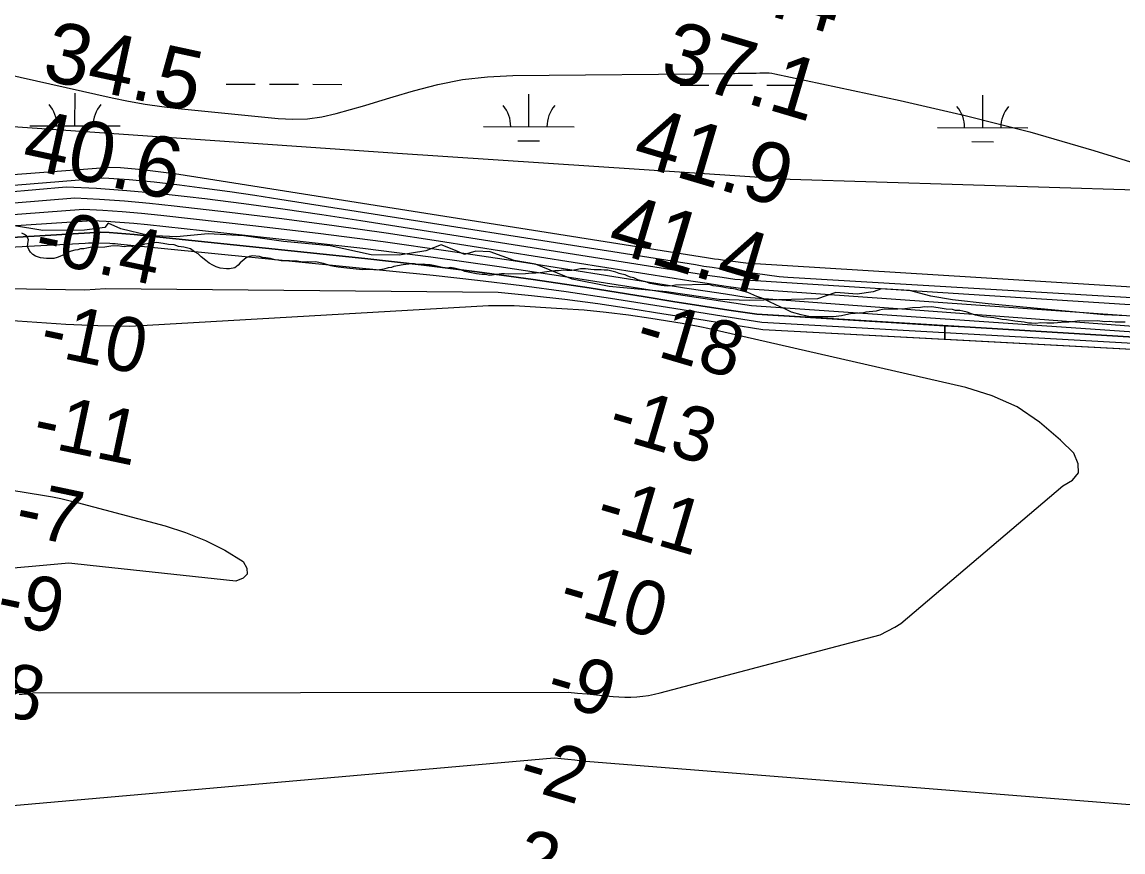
# Model space of a CAD drawing. Extents: x 3219052 to 3256913, y 800770 to 826146.
# Drawn here: x 3234446 to 3235663, y 812399 to 813316 of the extents above; entities that cross this region are included whole.
import ezdxf

# ---------------------------------------------------------------- set-up
doc = ezdxf.new("R2010")
doc.units = 0
for name, color, linetype in [('V-RIVR-EDGE', 7, 'Continuous'), ('V-RIVR-RANG', 7, 'Continuous'), ('V-SITE-VEGE', 7, 'Continuous'), ('V-TOPO-DPTH', 7, 'Continuous'), ('V-TOPO-MAJR', 7, 'Continuous'), ('V-TOPO-MINR', 7, 'Continuous'), ('V-TOPO-WATR', 7, 'Continuous'), ('V-WETL-SWMP', 7, 'Continuous')]:
    doc.layers.add(name, color=color, linetype=linetype)

msp = doc.modelspace()

# ---------------------------------------------------------------- linework, layer by layer
at = {"layer": 'V-RIVR-EDGE'}
for points in [[(3235514.1, 813004.7), (3235474.9, 813009.1), (3235450.8, 813013.5), (3235427.1, 813019.5), (3235396.3, 813021.6), (3235387.2, 813018), (3235369.4, 813015.7), (3235345.7, 813017.4), (3235325.5, 813010.3), (3235282.4, 813009.2), (3235250, 813008.5), (3235216.8, 813009.8), (3235158.7, 813018.2), (3235095.1, 813023.9), (3235054.4, 813032.3), (3235013.7, 813048.6), (3234990, 813052.6), (3234963.5, 813062.2), (3234947.7, 813063), (3234935, 813059.5), (3234925.2, 813063.9), (3234909.4, 813070.2), (3234892.3, 813063.5), (3234863.1, 813058.5), (3234831.8, 813058.9), (3234786.8, 813068.9), (3234735, 813073.8), (3234691.2, 813079.9), (3234651.6, 813082.3), (3234616.8, 813078.9), (3234585.6, 813080.5), (3234555.2, 813087.7), (3234541, 813094.1), (3234537.4, 813089.3), (3234514.9, 813086.2), (3234469, 813085.9), (3234435.4, 813091.6)], [(3237235.9, 812894.1), (3237149.3, 812895.9), (3236960.7, 812904.2), (3236846.1, 812912.4), (3236753.2, 812915.4), (3236688.4, 812916.8), (3236537.8, 812930.6), (3236373.4, 812945.2), (3236288.8, 812949.4), (3236142.9, 812959.6), (3235992.3, 812973.1), (3235916.8, 812980), (3235840.6, 812985.7), (3235793.5, 812987.8), (3235725.5, 812989.1), (3235642.5, 812992.5), (3235514.1, 813004.7)]]:
    msp.add_lwpolyline(points, dxfattribs=at)
at = {"layer": 'V-SITE-VEGE'}
for points in [[(3234570.5, 813067.3), (3234567.2, 813068.2), (3234562.9, 813068.6), (3234559.6, 813068), (3234556.3, 813068.4), (3234551.5, 813068.8), (3234543.9, 813068.7), (3234537.3, 813067.6), (3234521.2, 813067.3), (3234517.4, 813066.3), (3234514.1, 813065.7), (3234510.7, 813065.7), (3234507.4, 813064.7), (3234504.1, 813064.1), (3234500.3, 813063.1), (3234497, 813062.1), (3234491.4, 813058.6), (3234490.9, 813058.6), (3234487.6, 813057.2), (3234484.8, 813056.1), (3234481, 813055.1), (3234473, 813055), (3234466.3, 813055.8), (3234460.6, 813057.6), (3234457.7, 813059.4), (3234455.3, 813061.8), (3234453.3, 813065), (3234451.8, 813068.3), (3234452.2, 813071.7), (3234453.1, 813075.5), (3234451.1, 813079.7), (3234448.7, 813081.6), (3234445.8, 813082.9)], [(3235089.5, 813042), (3235086.2, 813042.4), (3235078.6, 813042.3), (3235074.8, 813042.7), (3235069.1, 813043.5), (3235063.4, 813043.4), (3235058.2, 813042.4), (3235053.9, 813041.8), (3235048.2, 813041.7), (3235044.9, 813042.1), (3235039.2, 813041.5), (3235034.9, 813041.4), (3235031.6, 813040.9), (3235026.4, 813040.3), (3235018.8, 813039.2), (3235014.1, 813038.7), (3235009.3, 813038.6), (3235002.7, 813038), (3234983.7, 813037.6), (3234979.4, 813038), (3234976.1, 813038), (3234970.4, 813037.4), (3234963.3, 813036.3), (3234958.1, 813037.1), (3234954.3, 813037.1), (3234948.6, 813037.9), (3234935.7, 813040.5), (3234932.4, 813041.9), (3234929.5, 813042.8), (3234923.8, 813044.1), (3234919.5, 813044.9), (3234917.1, 813044.4), (3234915.7, 813044.4), (3234911.9, 813044.8), (3234907.6, 813045.7), (3234902.8, 813047), (3234897.1, 813047.8), (3234893.8, 813047.8), (3234889.5, 813048.6), (3234883.3, 813048.5), (3234880, 813048.9), (3234876.7, 813048.9), (3234867.2, 813047.8), (3234857.2, 813046.1), (3234854.4, 813045.1), (3234850.6, 813044.6), (3234845.9, 813043.1), (3234838.8, 813042), (3234835, 813042.4), (3234827.4, 813042.7), (3234822.2, 813042.6), (3234805.1, 813044.2), (3234795.5, 813045.4), (3234791.2, 813046.3), (3234787.4, 813046.7), (3234779.3, 813049.4), (3234775.5, 813050.3), (3234770.7, 813051.1), (3234765, 813051), (3234761.2, 813051.4), (3234757.9, 813050.9), (3234754.1, 813051.3), (3234750.3, 813052.2), (3234746.5, 813052.1), (3234741.7, 813052.5), (3234732.3, 813052.3), (3234728.9, 813053.2), (3234725.6, 813053.6), (3234720.8, 813054.9), (3234715.6, 813055.8), (3234711.8, 813056.2), (3234708.4, 813057.1), (3234700.8, 813057.9), (3234697, 813057.3), (3234693.7, 813055.8), (3234691.4, 813053.9), (3234687.2, 813050), (3234684.9, 813047.6), (3234681.1, 813044.7), (3234675.4, 813043.6), (3234672.1, 813043.6), (3234665, 813044.4), (3234660.7, 813045.7), (3234656.9, 813047.5), (3234653, 813049.8), (3234649.2, 813052.6), (3234643.9, 813056.8), (3234640.5, 813060.1), (3234636.6, 813062.4), (3234632.3, 813065.6), (3234629.4, 813066.5), (3234624.7, 813067.4), (3234618.9, 813068.2), (3234614.2, 813070), (3234608, 813070.4), (3234601.8, 813071.7), (3234594.7, 813072.5), (3234584.7, 813071.3), (3234581.4, 813070.8), (3234576.7, 813068.8), (3234570.5, 813067.3)], [(3235665.6, 812984.6), (3235654.7, 812984.4), (3235648, 812985.2), (3235643.3, 812985.1), (3235635.2, 812985.9), (3235620.5, 812985.6), (3235614.8, 812986), (3235610, 812985.4), (3235607.7, 812984.9), (3235606.7, 812984.9), (3235603.4, 812984.4), (3235594.9, 812984.2), (3235586.8, 812983.6), (3235579.2, 812983.4), (3235572.6, 812983.8), (3235566.9, 812983.2), (3235562.1, 812983.6), (3235558.8, 812983.5), (3235554, 812984.4), (3235543.6, 812985.6), (3235534.5, 812987.3), (3235529.7, 812987.7), (3235520.7, 812989.4), (3235509.3, 812990.6), (3235503.6, 812991.5), (3235500.2, 812992.4), (3235495.9, 812993.7), (3235491.1, 812995.5), (3235486.4, 812996.8), (3235483, 812997.3), (3235478.3, 812997.6), (3235474.9, 812998.5), (3235467.8, 812998.9), (3235463.5, 812999.7), (3235452.1, 813001.4), (3235447.3, 813001.3), (3235444, 813001.7), (3235439.3, 813000.7), (3235430.7, 813000.5), (3235422.2, 812999.4), (3235414.2, 812998.8), (3235397.5, 812998.5), (3235394.2, 812997.9), (3235390.5, 812996.9), (3235379.1, 812995.8), (3235375.3, 812994.7), (3235371.5, 812994.7), (3235367.2, 812994.1), (3235363.9, 812994), (3235360.1, 812993.5), (3235352.1, 812991.4), (3235343.1, 812990.3), (3235339.8, 812990.3), (3235334.1, 812990.6), (3235320.3, 812990.4), (3235316, 812990.8), (3235310.8, 812992.1), (3235307.4, 812992.5), (3235296.9, 812995.6), (3235289.3, 812999.3), (3235285, 813001.1), (3235272.5, 813007), (3235268.2, 813009.3), (3235263.9, 813011.1), (3235258.6, 813012.9), (3235248.6, 813017.5), (3235244.3, 813018.4), (3235234.7, 813021), (3235230.4, 813021.9), (3235229, 813021.9), (3235224.3, 813022.7), (3235220.9, 813023.1), (3235216.6, 813024), (3235210, 813024.8), (3235205.7, 813026.2), (3235168.6, 813025.5), (3235164.9, 813024.9), (3235159.2, 813024.3), (3235152.5, 813025.2), (3235140.6, 813027.3), (3235135.8, 813029.1), (3235131, 813030.4), (3235126.7, 813031.3), (3235122.4, 813033.6), (3235118.6, 813034.5), (3235115.8, 813035.4), (3235112.9, 813036.8), (3235109.1, 813037.6), (3235106.2, 813038.5), (3235102.4, 813039.9), (3235093.8, 813042.1), (3235089.5, 813042)]]:
    msp.add_lwpolyline(points, dxfattribs=at)
at = {"layer": 'V-TOPO-DPTH'}
for points in [[(3237344.9, 812861.8), (3236561.3, 812952.3), (3235930.8, 812960.8), (3235246.7, 813012), (3235223.9, 813015.4), (3235201.3, 813018.8), (3235178.6, 813022.3), (3235155.9, 813025.9), (3234989.1, 813052.3), (3234917.3, 813063.2), (3234845.4, 813073.4), (3234773.3, 813082.6), (3234701.2, 813091.2), (3234599.5, 813102.6), (3234578.1, 813104.8), (3234556.7, 813106.6), (3234535.2, 813108), (3234513.8, 813109.1), (3233933.3, 813065.3)], [(3233911.8, 813046.7), (3234533.2, 813084.1), (3234542.4, 813083.6), (3234551.6, 813083.1), (3234560.8, 813082.3), (3234569.9, 813081.5), (3234824.9, 813055), (3234887.1, 813048), (3234949.2, 813040.3), (3235011.1, 813031.7), (3235073, 813022.4), (3235134.8, 813012.5), (3235165.7, 813007.6), (3235196.6, 813002.8), (3235227.5, 812998), (3235258.4, 812993.3), (3235466.3, 812980.7)], [(3233911.8, 813046.7), (3234533.2, 813084.1), (3234542.4, 813083.6), (3234551.6, 813083.1), (3234560.8, 813082.3), (3234569.9, 813081.5), (3234824.9, 813055), (3234887.1, 813048), (3234949.2, 813040.3), (3235011.1, 813031.7), (3235073, 813022.4), (3235134.8, 813012.5), (3235165.7, 813007.6), (3235196.6, 813002.8), (3235227.5, 812998), (3235258.4, 812993.3), (3235881.3, 812955.5), (3235890.2, 812953.3), (3235899.1, 812951), (3235908, 812948.6), (3236573.2, 812923.8), (3237329.4, 812836.9)], [(3235880.2, 812943.3), (3235265.2, 812976.2), (3235228.7, 812982), (3235192.2, 812987.8), (3235155.7, 812993.6), (3235119.1, 812999.5), (3235082.6, 813004.9), (3235046, 813009.8), (3235009.2, 813013.8), (3234972.4, 813017.2), (3234538.1, 813021.6), (3234515.3, 813019.9), (3233893.1, 813030.8)], [(3235466.3, 812980.7), (3235466.4, 812965.4), (3235265.2, 812976.2), (3235228.7, 812982), (3235192.2, 812987.8), (3235155.7, 812993.6), (3235119.1, 812999.5), (3235082.6, 813004.9), (3235046, 813009.8), (3235009.2, 813013.8), (3234972.4, 813017.2), (3234538.1, 813021.6), (3234515.3, 813019.9), (3233893.1, 813030.8)], [(3235880.2, 812943.3), (3235487.5, 812964.3), (3235466.4, 812965.4), (3235466.3, 812980.7), (3235488.4, 812979.3)], [(3235488.4, 812979.3), (3235881.3, 812955.5), (3235890.2, 812953.3), (3235899.1, 812951), (3235908, 812948.6), (3236573.2, 812923.8), (3237329.4, 812836.9), (3237410.6, 812838.4)], [(3233916.2, 812404.4), (3235034.5, 812503), (3235042, 812502.2), (3235049.6, 812501.4), (3235057.1, 812500.5), (3235064.6, 812499.7), (3235963, 812427.9)], [(3233916.2, 812404.4), (3235034.5, 812503), (3235042, 812502.2), (3235049.6, 812501.4), (3235057.1, 812500.5), (3235064.6, 812499.7), (3235963, 812427.9)]]:
    msp.add_lwpolyline(points, dxfattribs=at)
at = {"layer": 'V-TOPO-MAJR'}
msp.add_lwpolyline([(3235934.9, 812996), (3235292.6, 813034), (3235283.1, 813034.8), (3235227.4, 813042.3), (3235218.1, 813043.6), (3235208.9, 813044.9), (3235199.7, 813046.3), (3235190.5, 813047.8), (3234731.1, 813120.3), (3234703.4, 813124.6), (3234675.6, 813128.6), (3234647.8, 813132.4), (3234620, 813136), (3234592.1, 813139.2), (3234564.2, 813141.8), (3234536.3, 813143.8), (3233992.6, 813099.7)], dxfattribs=at)
at = {"layer": 'V-TOPO-MINR'}
for points in [[(3234341.8, 813278.4), (3234545.4, 813232.7), (3234563.6, 813229), (3234581.9, 813225.7), (3234600.3, 813223), (3234618.7, 813220.8), (3234729, 813209.6), (3234745.2, 813208.9), (3234761.4, 813209.4), (3234777.4, 813211.7), (3234793.3, 813215.2), (3234809.1, 813219.7), (3234824.9, 813224.2), (3234840.6, 813228.9), (3234856.4, 813233.6), (3234878.7, 813240.4), (3234905.7, 813247.4), (3234933, 813252.8), (3234960.7, 813255.9), (3234988.6, 813257.3), (3235229.9, 813259.7), (3235233.9, 813259.7), (3235237.9, 813259.8), (3235241.9, 813259.8), (3235245.9, 813259.8), (3235249.9, 813259.9), (3235253.9, 813259.9), (3235257.9, 813260), (3235261.9, 813260.2), (3235266, 813260.3), (3235269.1, 813260.3), (3235272.1, 813260.2), (3235275.2, 813259.8), (3235278.2, 813259.3), (3235416.8, 813229.7), (3235488.7, 813213.1), (3235560.3, 813195), (3235631.2, 813174.5), (3235701.7, 813152.5)], [(3235959, 813005.6), (3235250.7, 813049.3), (3235246.3, 813049.7), (3235220.4, 813053.1), (3235216, 813053.7), (3235211.7, 813054.3), (3235207.3, 813054.9), (3235202.9, 813055.6), (3234638.1, 813144.8), (3234626.3, 813146.7), (3234614.4, 813148.4), (3234602.5, 813150.1), (3234590.6, 813151.6), (3234578.7, 813153), (3234566.8, 813154.2), (3234554.8, 813155.1), (3234542.9, 813155.7), (3233935.1, 813109.7)], [(3237395, 812876.9), (3236548.6, 812982), (3236108.2, 812975.9), (3235234, 813031.9), (3235220.2, 813033.9), (3235206.3, 813035.9), (3235192.4, 813038), (3235178.6, 813040.2), (3234820.4, 813096.8), (3234777.4, 813103.4), (3234734.4, 813109.6), (3234691.3, 813115.3), (3234648.1, 813120.8), (3234628.6, 813123.1), (3234595.2, 813126.8), (3234561.7, 813129.9), (3234528.2, 813132.2), (3234494.6, 813133.9), (3233957.5, 813086.5)], [(3237356.7, 812873.6), (3236555, 812967), (3235922.2, 812973.7), (3235240.5, 813021.8), (3235222.1, 813024.5), (3235203.7, 813027.2), (3235185.4, 813030), (3235167, 813032.9), (3234906.3, 813074.2), (3234848.6, 813082.9), (3234790.9, 813091.2), (3234733.1, 813098.8), (3234675.2, 813105.9), (3234614.1, 813113), (3234586.7, 813115.8), (3234559.2, 813118.3), (3234531.7, 813120.1), (3234504.1, 813121.6), (3233945.1, 813075.6)], [(3237344.9, 812861.8), (3236561.3, 812952.3), (3235930.8, 812960.8), (3235246.7, 813012), (3235223.9, 813015.4), (3235201.3, 813018.8), (3235178.6, 813022.3), (3235155.9, 813025.9), (3234989.1, 813052.3), (3234917.3, 813063.2), (3234845.4, 813073.4), (3234773.3, 813082.6), (3234701.2, 813091.2), (3234599.5, 813102.6), (3234578.1, 813104.8), (3234556.7, 813106.6), (3234535.2, 813108), (3234513.8, 813109.1), (3233933.3, 813065.3)], [(3237322.3, 812854.4), (3236567.3, 812937.9), (3235918.6, 812954.2), (3235905.8, 812957.5), (3235252.6, 813002.5), (3235225.7, 813006.6), (3235198.9, 813010.7), (3235172, 813014.8), (3235145.2, 813019.1), (3235048.6, 813034.4), (3234973.4, 813045.8), (3234898.1, 813056.4), (3234822.6, 813065.9), (3234747, 813074.6), (3234584.8, 813092.1), (3234569.5, 813093.6), (3234554.1, 813094.9), (3234538.8, 813095.9), (3234523.4, 813096.6), (3233905.2, 813055.9)], [(3235876.7, 812949.7), (3235264, 812984.3), (3235229.1, 812989.7), (3235194.3, 812995.2), (3235159.5, 813000.7), (3235124.7, 813006.2), (3235096.6, 813010.7), (3235047.7, 813018), (3234998.7, 813024.8), (3234949.6, 813030.8), (3234900.5, 813036.1), (3234555, 813070.6), (3234552, 813070.9), (3234549, 813071.1), (3234546, 813071.3), (3234543, 813071.4), (3234526.4, 813072.1), (3234522.8, 813072), (3234519.3, 813071.8), (3234515.7, 813071.4), (3233893.8, 813038.7)], [(3235151.6, 812574.7), (3235395, 812638.8), (3235411, 812647.3), (3235417.8, 812651.5), (3235597, 812803.5), (3235607.7, 812810), (3235614, 812817.9), (3235613.7, 812828), (3235608.9, 812839.6), (3235594.4, 812854.2), (3235571.1, 812874), (3235546.2, 812890.8), (3235518.8, 812903.1), (3235489.7, 812912.4), (3235204.2, 812977.4), (3235197.1, 812979), (3235190, 812980.4), (3235182.9, 812981.7), (3235175.8, 812983), (3235141.1, 812988.6), (3235116.6, 812992.2), (3235092, 812995.3), (3235067.4, 812997.7), (3235042.7, 812999.5), (3234990, 813002.5), (3234961.9, 813002.8), (3234565, 812979.7), (3234547.3, 812980), (3234529.6, 812980.5), (3234511.9, 812981.2), (3234494.2, 812982.1), (3233884.8, 813024)], [(3235880.2, 812943.3), (3235265.2, 812976.2), (3235228.7, 812982), (3235192.2, 812987.8), (3235155.7, 812993.6), (3235119.1, 812999.5), (3235082.6, 813004.9), (3235046, 813009.8), (3235009.2, 813013.8), (3234972.4, 813017.2), (3234538.1, 813021.6), (3234515.3, 813019.9), (3233893.1, 813030.8)], [(3234375.5, 812808.4), (3234470.6, 812793), (3234479.7, 812791.4), (3234488.7, 812789.6), (3234497.7, 812787.5), (3234506.7, 812785.3), (3234604, 812759.4), (3234626.8, 812752.1), (3234648.9, 812743.3), (3234670, 812732.4), (3234690.4, 812720.1), (3234694.4, 812712.5), (3234694.9, 812706.1), (3234690.4, 812701.6), (3234682.4, 812698.3), (3234521.4, 812715.6), (3234497.8, 812718.1), (3233862.2, 812660.5)], [(3234442.8, 812573.1), (3234446.1, 812573.3), (3234450, 812573.5), (3234452.1, 812573.7), (3234456, 812574.4), (3234458, 812574.8), (3235049.7, 812575.3), (3235060.2, 812574.4), (3235070.7, 812573.5), (3235081.2, 812572.5), (3235091.6, 812571.5), (3235099.5, 812570.7), (3235106, 812570.2), (3235112.6, 812569.9), (3235119.2, 812569.9), (3235125.7, 812570.2), (3235132.3, 812570.9), (3235138.8, 812571.8), (3235145.2, 812573.1), (3235151.6, 812574.7)], [(3233916.2, 812404.4), (3235034.5, 812503), (3235042, 812502.2), (3235049.6, 812501.4), (3235057.1, 812500.5), (3235064.6, 812499.7), (3235963, 812427.9)]]:
    msp.add_lwpolyline(points, dxfattribs=at)
at = {"layer": 'V-TOPO-WATR'}
msp.add_lwpolyline([(3237329.4, 812836.9), (3236573.2, 812923.8), (3235908, 812948.6), (3235899.1, 812951), (3235890.2, 812953.3), (3235881.3, 812955.5), (3235258.4, 812993.3), (3235227.5, 812998), (3235196.6, 813002.8), (3235165.7, 813007.6), (3235134.8, 813012.5), (3235073, 813022.4), (3235011.1, 813031.7), (3234949.2, 813040.3), (3234887.1, 813048), (3234824.9, 813055), (3234569.9, 813081.5), (3234560.8, 813082.3), (3234551.6, 813083.1), (3234542.4, 813083.6), (3234533.2, 813084.1), (3233911.8, 813046.7)], dxfattribs=at)
at = {"layer": 'V-WETL-SWMP'}
for p, q in [((3234671.6, 813247.8), (3234703.6, 813247.7)), ((3234719.6, 813247.7), (3234751.6, 813247.6)), ((3234767.6, 813247.6), (3234799.6, 813247.5)), ((3235173.5, 813246.7), (3235205.5, 813246.7)), ((3235221.5, 813246.6), (3235253.5, 813246.6)), ((3235269.5, 813246.5), (3235301.5, 813246.5)), ((3234504.4, 813201.7), (3234504.5, 813237.7)), ((3235006.3, 813200.6), (3235006.4, 813236.6)), ((3235508.2, 813199.6), (3235508.3, 813235.6)), ((3234454.4, 813201.8), (3234554.4, 813201.6)), ((3234956.3, 813200.8), (3235056.3, 813200.5)), ((3235458.2, 813199.7), (3235558.2, 813199.5)), ((3234994.3, 813185.2), (3235018.3, 813185.2)), ((3235496.2, 813184.2), (3235520.2, 813184.1))]:
    msp.add_line(p, q, dxfattribs=at)
msp.add_lwpolyline([(3237234.2, 813214.6), (3236829, 813214.6), (3236669.9, 813156.7), (3236221.3, 813098.8), (3235772.7, 813127.7), (3235295.2, 813142.2), (3234861, 813171.2), (3234441.4, 813200.2), (3234150.4, 813217.3), (3234029.3, 813224.4), (3233949.4, 813229.1), (3233515.3, 813243.6), (3232922, 813243.6)], dxfattribs=at)
for centre, start, end in [((3234449.2, 813202.3), 359.1081, 40.6518), ((3234559.7, 813202.1), 139.1081, 180.6517), ((3234951.1, 813201.2), 359.1081, 40.6518), ((3235061.6, 813201), 139.1081, 180.6517), ((3235453, 813200.2), 359.1081, 40.6518), ((3235563.5, 813200), 139.1081, 180.6517)]:
    msp.add_arc(centre, 35.2, start, end, dxfattribs=at)

# ---------------------------------------------------------------- texts
at = {"layer": 'V-RIVR-RANG'}
for s, height, rotation, p in [('36.4', 67, 343.5183, (3235175.2, 813352.1)), ('34.5', 67, 347.8183, (3234466.4, 813253.3)), ('37.1', 67, 343.5183, (3235149.4, 813255.5)), ('40.6', 67, 347.8183, (3234443.7, 813155.8)), ('41.9', 67, 343.5183, (3235118.7, 813160.3)), ('41.4', 67, 343.5183, (3235090.8, 813064.3)), ('-0.4', 60, 348.0996, (3234457.4, 813053.7)), ('-10', 60, 348.0996, (3234463.4, 812950.3)), ('-18', 60, 343.5887, (3235121.6, 812954.5)), ('-13', 60, 343.5887, (3235091.2, 812859.2)), ('-11', 60, 348.0996, (3234455.5, 812849.7)), ('-7', 60, 348.0996, (3234435.8, 812751.7)), ('-11', 60, 343.5887, (3235077.7, 812758.9)), ('-9', 60, 348.0996, (3234415.1, 812653.9)), ('-10', 60, 343.5887, (3235036.9, 812666.7)), ('-8', 60, 348.0996, (3234393.6, 812556.2)), ('-9', 60, 343.5887, (3235022.8, 812566.6)), ('-2', 60, 343.5887, (3234992.2, 812471.3)), ('2', 60, 343.5887, (3234986.7, 812368.7))]:
    msp.add_text(s, height=height, rotation=rotation, dxfattribs=at).set_placement(p)

doc.saveas('drawing.dxf')
